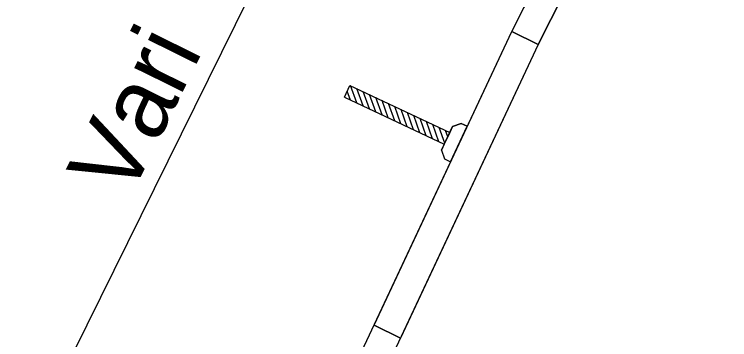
# Model space of a CAD drawing. Extents: x 14104283 to 14121738, y 8635219 to 8671666.
# Drawn here: x 14117454.1 to 14117535.2, y 8667362.6 to 8667399.4 of the extents above; entities that cross this region are included whole.
import ezdxf

# ---------------------------------------------------------------- set-up
doc = ezdxf.new("R2010")
doc.units = 0
for name, color, linetype in [('Cell', 7, 'Continuous'), ('Default', 7, 'Continuous'), ('dsnStgShadingPrevPav', 7, 'Continuous'), ('dsnTextFinalPlan', 7, 'Continuous'), ('TC_SubstrataExistingPavement', 7, 'Continuous'), ('Terrain', 7, 'Continuous')]:
    doc.layers.add(name, color=color, linetype=linetype)

msp = doc.modelspace()

# ---------------------------------------------------------------- linework, layer by layer
at = {"layer": 'Cell'}
for p, q in [((14117491.526, 8667390.051), (14117492.159, 8667391.395)), ((14117492.2, 8667389.733), (14117491.844, 8667390.726)), ((14117492.159, 8667391.395), (14117503.49, 8667386.055)), ((14117492.919, 8667389.395), (14117492.208, 8667391.371)), ((14117493.637, 8667389.056), (14117492.927, 8667391.033)), ((14117494.355, 8667388.718), (14117493.645, 8667390.694)), ((14117491.526, 8667390.051), (14117502.857, 8667384.711)), ((14117495.074, 8667388.379), (14117494.363, 8667390.356)), ((14117495.792, 8667388.041), (14117495.082, 8667390.017)), ((14117496.51, 8667387.702), (14117495.8, 8667389.679)), ((14117497.229, 8667387.364), (14117496.518, 8667389.34)), ((14117497.947, 8667387.025), (14117497.237, 8667389.002)), ((14117498.665, 8667386.687), (14117497.955, 8667388.663)), ((14117499.384, 8667386.348), (14117498.674, 8667388.324)), ((14117500.102, 8667386.009), (14117499.392, 8667387.986)), ((14117500.821, 8667385.671), (14117500.11, 8667387.647)), ((14117501.539, 8667385.332), (14117500.829, 8667387.309)), ((14117502.257, 8667384.994), (14117501.547, 8667386.97)), ((14117502.913, 8667384.83), (14117502.265, 8667386.632)), ((14117502.54, 8667384.039), (14117503.807, 8667386.726)), ((14117503.807, 8667386.726), (14117503.49, 8667386.055)), ((14117503.557, 8667382.74), (14117505.456, 8667386.77)), ((14117503.557, 8667382.74), (14117505.456, 8667386.77)), ((14117504.79, 8667387.084), (14117503.807, 8667386.726)), ((14117503.807, 8667386.726), (14117504.79, 8667387.084)), ((14117505.456, 8667386.77), (14117504.79, 8667387.084)), ((14117504.79, 8667387.084), (14117505.456, 8667386.77)), ((14117503.49, 8667386.055), (14117502.857, 8667384.711)), ((14117503.251, 8667385.548), (14117502.984, 8667386.293)), ((14117502.857, 8667384.711), (14117502.54, 8667384.039)), ((14117502.54, 8667384.039), (14117502.89, 8667383.054)), ((14117502.54, 8667384.039), (14117502.89, 8667383.054)), ((14117502.89, 8667383.054), (14117503.557, 8667382.74)), ((14117502.89, 8667383.054), (14117503.557, 8667382.74))]:
    msp.add_line(p, q, dxfattribs=at)
at = {"layer": 'Default'}
msp.add_lwpolyline([(14117510.53, 8667397.502), (14117510.53, 8667397.502), (14117532.252, 8667440.377), (14117535.241, 8667438.899), (14117523.469, 8667415.665), (14117513.518, 8667396.025), (14117513.518, 8667396.025)], close=True, dxfattribs=at)
at = {"layer": 'dsnStgShadingPrevPav'}
msp.add_lwpolyline([(14117494.901, 8667364.234), (14117510.53, 8667397.502), (14117513.518, 8667396.025), (14117497.889, 8667362.756)], close=True, dxfattribs=at)
at = {"layer": 'dsnTextFinalPlan'}
msp.add_line((14117460.83, 8667361.184), (14117485.08, 8667410.231), dxfattribs=at)
at = {"layer": 'TC_SubstrataExistingPavement'}
msp.add_line((14117494.901, 8667364.234), (14117497.889, 8667362.756), dxfattribs=at)
for points in [[(14117513.518, 8667396.025), (14117523.469, 8667415.665), (14117535.241, 8667438.899)], [(14117510.53, 8667397.502), (14117513.518, 8667396.025), (14117457.062, 8667275.849), (14117454.074, 8667277.326)]]:
    msp.add_lwpolyline(points, dxfattribs=at)
at = {"layer": 'Terrain'}
msp.add_line((14117454.074, 8667277.326), (14117510.53, 8667397.502), dxfattribs=at)
msp.add_lwpolyline([(14117510.53, 8667397.502), (14117520.481, 8667417.143), (14117532.252, 8667440.377)], dxfattribs=at)

# ---------------------------------------------------------------- texts
at = {"layer": 'dsnTextFinalPlan'}
msp.add_text('Vari', height=8, rotation=63.69111, dxfattribs=at).set_placement((14117467.062, 8667378.263))

doc.saveas('drawing.dxf')
